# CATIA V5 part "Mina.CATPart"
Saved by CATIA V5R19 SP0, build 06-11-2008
Material "Gold": density 19320 kg/m3, Young's modulus 7.8e+10 Pa, Poisson ratio 0.42, thermal expansion 1.42e-05 1/K
Bounding box of the stored display mesh (mm): x -1.5 to 1.5, y -1.5 to 1.5, z -14 to 0
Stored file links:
  D:\F&IC\cursos\06 - EJERCICIOS\EJERCICIOS3D.COM\04_ASSEMBLY\TERMINADOS\0171-BOLIGRAFO\MODELOS\Mina.CATPart
  C:\Program Files (x86)\Dassault Systemes\B19\intel_a\startup\materials\Catalog.CATMaterial
  D:\F&IC\cursos\06 - EJERCICIOS\EJERCICIOS3D.COM\04_ASSEMBLY\TERMINADOS\0171-BOLIGRAFO\MODELOS\Grupo boligrafo.CATProduct
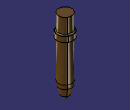
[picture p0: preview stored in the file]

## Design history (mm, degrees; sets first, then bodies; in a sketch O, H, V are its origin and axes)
AxisSystem1: origin (0, 0, 0), X (1, 0, 0), Y (0, 1, 0), Z (0, 0, 1)
Body1 "PartBody" (main body)
  Sketch1 on YZ plane of AxisSystem1, origin (0, 0, 0), H (0, 1, 0), V (0, 0, 1)
    line L1 (0, 0) -> (-1.25, 0)
    point P1 (-1.25, 0)
    line L2 (-1.25, 0) -> (-1.25, -2.8)
    point P2 (-1.25, -3)
    line L3 (-1.45, -3) -> (-1.5, -3)
    line L4 (-1.5, -3) -> (-1.5, -4)
    line L5 (-1.5, -4) -> (-1.45, -4)
    point P5 (-1.25, -4)
    line L6 (-1.25, -4.2) -> (-1.25, -11.1792)
    point P6 (-0.6, -14)
    construction line L7 (-0.6, -14) -> (0, -14)
    point P7 (0, -14)
    axis line L8 (0, 2.6236) -> (0, -15.4105)
    point P8 (0, 2.6236)
    line L9 (-0.7553, -13.4204) -> (-1.1478, -11.9557)
    arc A1 centre (1.75, -11.1792) radius 3 from (-1.1478, -11.9557) to (-1.25, -11.1792) cw
    construction line L10 (-1.1478, -11.9557) -> (-1.25, -11.5742)
    construction line L11 (-1.25, -11.1792) -> (-1.25, -11.5742)
    arc A2 centre (0, -13.2181) radius 0.7819 from (-0.7553, -13.4204) to (0, -14) ccw
    point P14 (0, -13.2181)
    arc A3 centre (-1.45, -4.2) radius 0.2 from (-1.45, -4) to (-1.25, -4.2) cw
    construction line L12 (-1.45, -4) -> (-1.25, -4)
    construction line L13 (-1.25, -4) -> (-1.25, -4.2)
    arc A4 centre (-1.45, -2.8) radius 0.2 from (-1.25, -2.8) to (-1.45, -3) cw
    construction line L14 (-1.25, -2.8) -> (-1.25, -3)
    construction line L15 (-1.25, -3) -> (-1.45, -3)
    distance L2 V = 1.25
    distance L4 L8 = 1.5
    distance L7 P5 = 10
    length L4 = 1
    length L7 = 0.6
    angle L9 L8 = 15
    radius A1 = 3
    radius A3 = 0.2
    distance P1 P2 = 3
    radius A4 = 0.2
    horizontal: L1 H, L3 H, L5 H, L7 H
    vertical: L2 V, L4 V, L6 V, L8 V
    coincidence: P5 L2, P7 V, P8 V, L9 L10, L6 L11, P14 L8, P6 L9, L5 P5, L6 P5, L5 L12, L6 L13, L2 P2, L3 P2, L2 L14, L3 L15
    tangency: A1 L9, A1 L6, A2 L7, A2 L9, A3 L5, A3 L6, A4 L2, A4 L3
  Shaft1: profile Sketch1, axis Sketch1.L8, angle 360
